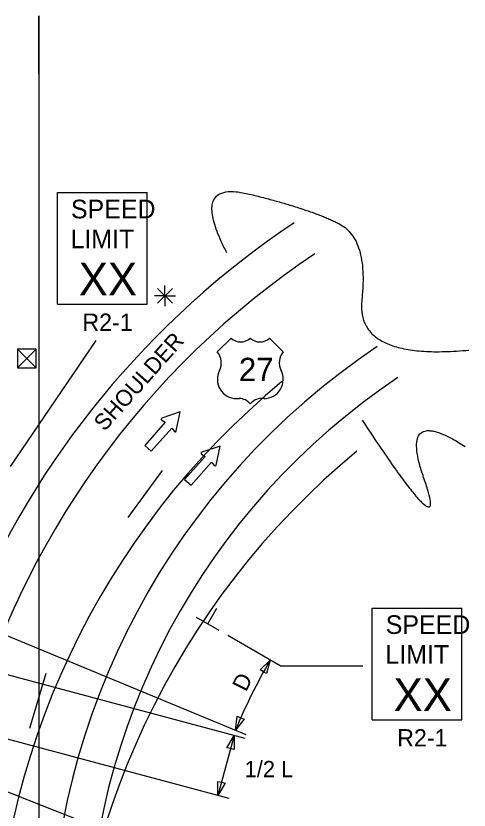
# Model space of a CAD drawing. Extents: x 16729 to 18500, y 5737 to 6974.
# Drawn here: x 16994.8 to 17189.2, y 6633.2 to 6974.1 of the extents above; entities that cross this region are included whole.
import ezdxf

# ---------------------------------------------------------------- set-up
doc = ezdxf.new("R2010")
doc.units = 0
for name, color, linetype in [('ALI_LEGAL_EX', 7, 'Continuous'), ('MT_SCRATCH_LEVEL_E', 7, 'Continuous'), ('PAVT_EDGE_EX', 7, 'Continuous'), ('TRAFFIC_SIGNS_PR', 7, 'Continuous'), ('TYPICAL_EX', 7, 'Continuous'), ('TYPICAL_TEXT_DIMEN_PR', 7, 'Continuous')]:
    doc.layers.add(name, color=color, linetype=linetype)

msp = doc.modelspace()

# ---------------------------------------------------------------- linework, layer by layer
at = {"layer": 'ALI_LEGAL_EX'}
for p, q in [((17004.68, 6974.12), (17004.68, 6155.98)), ((17004.68, 6891.53), (17004.68, 6027.61)), ((17007.7, 6691.9), (17000.71, 6668.24))]:
    msp.add_line(p, q, dxfattribs=at)
for points in [[(17004.68, 6949.12), (17004.68, 6974.12)], [(17043, 6758.79), (17057.75, 6778.98)]]:
    msp.add_lwpolyline(points, dxfattribs=at)
for centre in [(17325.51, 6555.03), (17357.65, 6525.15)]:
    msp.add_arc(centre, 340, 129.5666, 180, dxfattribs=at)
at = {"layer": 'MT_SCRATCH_LEVEL_E'}
for p, q in [((17065.34, 6804.16), (17057.46, 6801.48)), ((17063.63, 6795.99), (17065.34, 6804.16)), ((17058.9, 6799.7), (17050.1, 6789.79)), ((17057.36, 6800.64), (17058.9, 6799.7)), ((17052.89, 6787.3), (17061.7, 6797.21)), ((17061.7, 6797.21), (17062.82, 6795.8)), ((17050.1, 6789.79), (17052.89, 6787.3)), ((17082.42, 6789.5), (17074.54, 6786.82)), ((17080.72, 6781.33), (17082.42, 6789.5)), ((17075.99, 6785.04), (17067.18, 6775.13)), ((17074.45, 6785.99), (17075.99, 6785.04)), ((17069.98, 6772.65), (17078.78, 6782.56)), ((17078.78, 6782.56), (17079.9, 6781.14)), ((17067.18, 6775.13), (17069.98, 6772.65))]:
    msp.add_line(p, q, dxfattribs=at)
for centre, start, end in [((17057.61, 6801.04), 108.8028, 238.3418), ((17063.18, 6796.09), 218.4141, 348.1511), ((17074.7, 6786.38), 108.8028, 238.3418), ((17080.26, 6781.44), 218.4141, 348.1511)]:
    msp.add_arc(centre, 0.463, start, end, dxfattribs=at)
at = {"layer": 'PAVT_EDGE_EX'}
for radius, end in [(380, 157.5011), (364, 165.0045), (316, 180), (300, 180)]:
    msp.add_arc((17325.51, 6569.52), radius, 123.7854, end, dxfattribs=at)
at = {"layer": 'TRAFFIC_SIGNS_PR'}
for p, q in [((17012.67, 6898.36), (17051.07, 6898.36)), ((17012.67, 6850.36), (17012.67, 6898.36)), ((17051.07, 6850.36), (17051.07, 6898.36)), ((17012.67, 6850.36), (17051.07, 6850.36)), ((17147.68, 6719.98), (17186.08, 6719.98)), ((17147.68, 6671.98), (17147.68, 6719.98)), ((17186.08, 6671.98), (17186.08, 6719.98)), ((17147.68, 6671.98), (17186.08, 6671.98))]:
    msp.add_line(p, q, dxfattribs=at)
at = {"layer": 'TYPICAL_EX'}
for p, q in [((17081.21, 6829.94), (17087.1, 6835.84)), ((17109.51, 6829.94), (17103.61, 6835.84)), ((17089.45, 6809.88), (17090.63, 6809.88)), ((17101.26, 6809.88), (17100.08, 6809.88))]:
    msp.add_line(p, q, dxfattribs=at)
for centre, radius, start, end in [((17091.23, 6840.13), 5.96, 226.1404, 313.8596), ((17099.48, 6840.13), 5.96, 226.1404, 313.8596), ((17075.62, 6825.22), 7.31, 333.0977, 40.1936), ((17115.09, 6825.22), 7.31, 139.8064, 206.9023), ((17089.47, 6818.13), 8.24, 152.6698, 269.9013), ((17101.25, 6818.13), 8.24, 270.0987, 27.3302), ((17090.65, 6803.98), 5.91, 37.1038, 90.1385), ((17100.07, 6803.98), 5.91, 89.8615, 142.8962)]:
    msp.add_arc(centre, radius, start, end, dxfattribs=at)
at = {"layer": 'TYPICAL_TEXT_DIMEN_PR'}
for p, q in [((17061.96, 6857.16), (17055.58, 6850.78)), ((17055.59, 6857.16), (17061.96, 6850.78)), ((17058.77, 6853.97), (17058.77, 6858.43)), ((17058.77, 6853.97), (17054.24, 6853.97)), ((17058.77, 6853.97), (17061.96, 6853.97)), ((17058.77, 6853.97), (17063.25, 6853.97)), ((17058.77, 6853.97), (17058.77, 6849.47)), ((16992.47, 6780.68), (17029.33, 6834.75)), ((16995.58, 6831.02), (17003.58, 6823.02)), ((16995.58, 6823.02), (17003.58, 6831.02)), ((17077.17, 6713.12), (17081.06, 6719.86)), ((17082.04, 6710.31), (17072.29, 6715.93)), ((17093.61, 6665.56), (16977.03, 6713.85)), ((17108.22, 6695.16), (17085.71, 6708.17)), ((17099.6, 6693.37), (17103.89, 6697.66)), ((17103.89, 6697.66), (17102.32, 6691.8)), ((17108.22, 6695.16), (17143.57, 6695.16)), ((17093.19, 6664), (16981.21, 6693.99)), ((17100.96, 6692.59), (17099.6, 6693.37)), ((17102.32, 6691.8), (17100.96, 6692.59)), ((17088.99, 6667.48), (17089.79, 6673.49)), ((17092.69, 6672.29), (17088.99, 6667.48)), ((17089.79, 6673.49), (17091.24, 6672.89)), ((17091.24, 6672.89), (17092.69, 6672.29)), ((17086.29, 6638.21), (16982.82, 6665.93)), ((17088.41, 6665.28), (17081.5, 6639.5)), ((17085.37, 6660.03), (17088.41, 6665.28)), ((17088.41, 6665.28), (17088.41, 6659.21)), ((17086.89, 6659.62), (17085.37, 6660.03)), ((17088.41, 6659.21), (17086.89, 6659.62)), ((16964.45, 6651.69), (17046.11, 6619.48)), ((17081.5, 6639.5), (17081.5, 6645.57)), ((17081.5, 6645.57), (17083.02, 6645.16)), ((17084.53, 6644.75), (17081.5, 6639.5)), ((17083.02, 6645.16), (17084.53, 6644.75))]:
    msp.add_line(p, q, dxfattribs=at)
msp.add_lwpolyline([(16995.58, 6831.02), (16995.58, 6823.02), (17003.58, 6823.02), (17003.58, 6831.02)], close=True, dxfattribs=at)
msp.add_arc((17325.51, 6569.52), 256, 149.9625, 157.5013, dxfattribs=at)
for points in [[(17085.32, 6872.4), (17068.93, 6903.88), (17120.14, 6891.56), (17146.08, 6878.56), (17140.29, 6826.13), (17189.09, 6830.66)], [(17143.35, 6800.53), (17181.58, 6742.35), (17158.37, 6808.06), (17187.53, 6789.29)]]:
    msp.add_open_spline(points, degree=2, dxfattribs=at)

# ---------------------------------------------------------------- texts
at = {"layer": 'TRAFFIC_SIGNS_PR'}
for s, height, p in [('SPEED', 8, (17018.44, 6887.22)), ('LIMIT', 8, (17018.27, 6874.42)), ('XX', 14.031, (17021.78, 6854.12)), ('R2-1', 7.44, (17023.35, 6838.92)), ('SPEED', 8, (17153.45, 6708.85)), ('LIMIT', 8, (17153.28, 6696.05)), ('XX', 14.031, (17156.79, 6675.74)), ('R2-1', 7.44, (17158.36, 6660.54))]:
    msp.add_text(s, height=height, dxfattribs=at).set_placement(p)
at = {"layer": 'TYPICAL_EX'}
msp.add_text('27', height=10, dxfattribs=at).set_placement((17090.47, 6817.37))
at = {"layer": 'TYPICAL_TEXT_DIMEN_PR'}
for s, rotation, p in [('SHOULDER', 48.378, (17032.86, 6795.46)), ('D', 63.7334, (17093.58, 6683.72))]:
    msp.add_text(s, height=7, rotation=rotation, dxfattribs=at).set_placement(p)
msp.add_text('1/2 L', height=7, dxfattribs=at).set_placement((17092.94, 6647.35))

doc.saveas('drawing.dxf')
